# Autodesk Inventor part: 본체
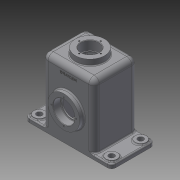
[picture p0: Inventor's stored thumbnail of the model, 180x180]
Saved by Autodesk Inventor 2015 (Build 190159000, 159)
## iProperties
Created: 2010-03
Part Number: 본체
Document SubType Name: Modeling
Designer: 진현석
Density: 2.71 g/cm^3
Material: 알루미늄 6061
Appearance: 알루미늄 - 평지
Author: 진현석
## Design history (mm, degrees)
sketch "스케치1"
  geometry: L1 (-62, 52)-(62, 52); L2 (62, 52)-(62, -52); L3 (62, -52)-(-62, -52); L4 (-62, -52)-(-62, 52); 3 further points
  constraints: 8 end point, 2 midpoint, 2 parallel, 1 horizontal, 1 horizontal alignment, 1 perpendicular, 1 vertical alignment
  dimensions: "d0" = 124 distance of L1.start L1.end; "d1" = 104 distance of L1.end L2.end
extrude "돌출1" new body sketch "스케치1" distance "d2" = 164; taper "d3" = 0 deg
fillet "모깎기9" dims "d55" = 13
feature "쉘2" dims "d54" = 10
sketch "스케치2"
  geometry: L1 (124, 0)-(0, 0) reference; C1 r 38 at (62, 75); 2 further points
  constraints: 1 centre point, 1 midpoint, 1 vertical alignment
  dimensions: "d5" = 76 diameter of C1; "d6" = 75 distance from line of L1 C1.centre
extrude "돌출2" join sketch "스케치2" distance "d7" = 11; taper "d8" = 0 deg
sketch "스케치13"
  geometry: L1 (-63, 37)-(-63, 113) reference; L2 (63, 37)-(63, 113) reference; L3 (-63, 75)-(63, 75); L4 (-63, 101)-(-46, 101); L5 (-45, 100)-(-45, 98); L6 (-45, 98)-(45, 98); L7 (45, 98)-(45, 100); L8 (46, 101)-(63, 101); L9 (-42, 0)-(-42, 151) reference; L10 (42, 151)-(42, 0) reference; A1 r 1 centre (46, 100) between (46, 101) and (45, 100); A2 r 1 centre (-46, 100) between (-45, 100) and (-46, 101); 1 further point
  constraints: 12 end point, 4 point on circle, 4 tangent, 3 parallel, 2 centre point, 2 midpoint, 2 perpendicular, 2 point on line, 1 collinear, 1 equal radius
  dimensions: "d77" = 3 distance between parallel lines of L5 L9; "d78" = 3 distance between parallel lines of L10 L7; "d79" = 52 diameter of L8 L3; "d80" = 3 distance between parallel lines of L6 L8; "d81" = 1 radius of A1
revolve "회전1" sketch "스케치13" stored, may be unused: angle "d82" = 90 deg
sketch "스케치4"
  geometry: L1 (62, 52)-(-62, 52) reference; L2 (-62, -52)-(62, -52) reference; L3 (-104, 52)-(104, 52); L4 (104, 52)-(104, -52); L5 (104, -52)-(-104, -52); L6 (-104, -52)-(-104, 52); L7 (-62, 39)-(-62, -39) reference; L8 (62, -39)-(62, 39) reference; A1 r 13 centre (-49, 39) between (-49, 52) and (-62, 39) reference; A2 r 13 centre (-49, -39) between (-62, -39) and (-49, -52) reference; A3 r 13 centre (49, -39) between (49, -52) and (62, -39) reference; A4 r 13 centre (49, 39) between (62, 39) and (49, 52) reference; 2 further points
  constraints: 8 end point, 2 collinear, 2 midpoint, 2 parallel, 1 horizontal, 1 perpendicular
  dimensions: "d11" = 208 distance of L4.end L5.end
extrude "돌출4" join sketch "스케치4" distance "d12" = 10; taper "d13" = 0 deg
sketch "스케치12"
  geometry: L1 (104, -52)-(49, -52) reference; L2 (104, 52)-(104, -52) reference; C1 r 13.5 at (87, -35); 1 further point
  constraints: 1 centre point
  dimensions: "d57" = 27 diameter of C1; "d58" = 17 distance from line of L1 C1.centre; "d59" = 17 distance from line of L2 C1.centre
extrude "돌출10" join sketch "스케치12" distance "d60" = 3; taper "d61" = 0 deg
hole "구멍2" diameter "d64" = 13.5; stored, may be unused: countersink angle "d68" = 90 deg, drill point angle "d70" = 118 deg; dims "d62" = 10, "d63" = 10, "d65" = 6, "d66" = 33, "d67" = 8.6, "d69" = 8
sketch "스케치9"
  geometry: C1 r 35 at (0, 0); 1 further point
  constraints: 1 centre point, 1 coincident
  dimensions: "d43" = 70 diameter of C1
extrude "돌출11" join sketch "스케치9" distance "d71" = 14; taper "d72" = 0 deg
sketch "스케치7"
  geometry: C1 r 21.5 at (0, 0); C2 r 35 at (0, 0) reference; 1 further point
  constraints: 1 centre point, 1 coincident, 1 concentric
  dimensions: "d23" = 43 diameter of C1
extrude "돌출12" cut sketch "스케치7" distance "d73" = 22; taper "d74" = 0 deg
sketch "스케치8"
  geometry: C1 r 38 at (0, 0) reference; 2 further points
  constraints: 1 vertical alignment
  dimensions: "d32" = 30 distance of C1.centre point (0, 30)
hole "구멍1" sketch "스케치8" at (0, 30) diameter "d33" = 3.242; stored, may be unused: countersink angle "d37" = 90 deg, drill point angle "d39" = 118 deg; dims "d34" = 8, "d35" = 4, "d36" = 2, "d38" = 10
fillet "모깎기1" dims "d26" = 10
fillet "모깎기10" dims "d75" = 3
fillet "모깎기11" dims "d76" = 3
fillet "모깎기7" dims "d50" = 3
chamfer "모따기2" distance "d83" = 1; stored, may be unused: second distance "d84" = 2, angle "d85" = 45 deg
chamfer "모따기3" distance "d86" = 1; stored, may be unused: second distance "d87" = 2, angle "d88" = 45 deg
fillet "모깎기12" dims "d89" = 2
sketch "스케치14"
  geometry: C1 r 19.5 at (0, 0); C2 r 21.5 at (0, 0) reference; 1 further point
  constraints: 1 centre point, 1 coincident
  dimensions: "d92" = 2 radial gap between concentric circles of C2 C1
extrude "돌출13" cut sketch "스케치14" stored distance "d93" = 10; taper "d94" = 0 deg
sketch "스케치15"
  geometry: C1 r 2.25 at (0, 26) reference; 1 further point
hole "구멍3" sketch "스케치15" at (0, 26) diameter "d95" = 3.242; stored, may be unused: countersink angle "d99" = 90 deg, drill point angle "d101" = 118 deg; dims "d96" = 8, "d97" = 4, "d98" = 2, "d100" = 10
sketch "스케치16"
  geometry: L1 (143, -151)-(-45, -151) reference; L2 (98, 13)-(0, 13) reference; 3 further points
  constraints: 1 midpoint, 1 vertical alignment, 1 other
  dimensions: "d105" = 20 distance from line of point (49, -7) L2
feature "엠보싱1" sketch "스케치16" dims "d0" = 124, "d1" = 104, "d106" = 0.5, "d107" = 0
node "솔리드1"
mirror "대칭1"
mirror "대칭5"
mirror "대칭6"
pattern_circular "원형 패턴1" dims angle "d41" = 360 deg
mirror "대칭4"
pattern_circular "원형 패턴2" dims angle "d103" = 360 deg
node "참조1"
